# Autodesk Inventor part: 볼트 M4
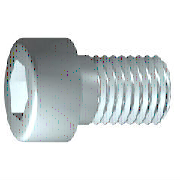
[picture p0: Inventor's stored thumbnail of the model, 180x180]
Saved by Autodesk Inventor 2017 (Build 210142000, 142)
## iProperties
IsCustomPart: 0
Created: 2012-02
Part Number: 볼트 M4
Material: 스테인리스강
Description: 6각 소켓 머리 캡 나사
Document SubType Name: Modeling
Standard: ISO 4762
Designer: mduedu
Standard Revision: Fourth edition 2004-03-01
Standards Organization: ISO
Language: ko-KR
Size Designation: M4 x 12
Categories: <MemberInstance><Categories><Category DisplayName="조임쇠" InternalName="e4da775c-781d-43d5-af7c-5136215cf5a6" Mnemonic="FSTN"><Category DisplayName="볼트" InternalN
Density: 8.08 g/cm^3
Mass: 2.2972 g
Surface Area: 3.30853 cm^2
Volume: 0.284306 cm^3
Appearance: 반광택
Author: mduedu
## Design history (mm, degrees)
sketch "스케치1"
  geometry: L1 (-1, 0)-(12, 0); L2 (12, 0)-(12, 2); L3 (12, 2)-(1.75, 2); L4 (1.75, 2)-(1.32, 2); L5 (1.32, 2)-(0, 2); L6 (0, 2)-(0, 3.5); L7 (0, 3.5)-(-4, 3.5); L8 (-4, 3.5)-(-4, 1.732); L9 (-4, 1.732)-(-2, 1.732); L10 (-2, 1.732)-(-1, 0); L11 (-7.2, 0)-(15.2, 0) reference; L12 (0, -0.7)-(0, 4.2) reference; L13 (1.75, 2)-(0, 2)
  constraints: 22 end point, 6 parallel, 2 collinear, 2 perpendicular, 1 horizontal, 1 point on line
  dimensions: "d1" = 10.25 distance from line of L3.end L2 (= GEL); "d2" = 0.42952 distance of L4.end L3.end (computed from GAL); "d3" = 4 distance between parallel lines of L8 L6 (= KOH); "d4" = 2 distance of L8.end L9.end (= INTI); "d5" = 60 deg angle of L10 L1; "d6" = 4 diameter of L3 L1 (= GD); "d7" = 4 diameter of L5 L1 (= BDM); "d8" = 3.4641 diameter of L9 L1 (= 1.1547 x SW); "d9" = 7 diameter of L7 L1 (= KOD); "d26" = 12 distance between parallel lines of L12 L2 (= NLG)
revolve "본체" sketch "스케치1" stored, may be unused: angle "d10" = 90 deg
sketch "스케치2"
  geometry: L1 (0, -4.9)-(0, 4.9) reference; L2 (-4.9, 0)-(4.9, 0) reference; L3 (1.732, 0)-(0.866, -1.5); L4 (0.866, -1.5)-(-0.866, -1.5); L5 (-0.866, -1.5)-(-1.732, 0); L6 (-1.732, 0)-(-0.866, 1.5); L7 (-0.866, 1.5)-(0.866, 1.5); L8 (0.866, 1.5)-(1.732, 0); 2 further points
  constraints: 12 end point, 1 coincident, 1 horizontal alignment, 1 point on line, 12 other
extrude "슬롯" join sketch "스케치2" stored distance "d11" = 10; taper "d12" = 0 deg
workplane "Work Plane1"
fillet "Fillet2" dims "d30" = 0.1 (= R)
body "Solid1"
fillet "모깎기1" dims "d17" = 0.4 (= RR)
feature "스레드" dims "d13" = 10.25 (= GEL), "d14" = 0
chamfer "모따기1" distance "d15" = 0.42941 (= -0.5 x SPD + 0.5 x GD); stored, may be unused: second distance "d16" = 0.42941 (= GUL), angle "d27" = 45 deg
other parameters: "GD" = 4 [user parameter; used in 2 equation terms], "NLG" = 12 [user parameter; used in 1 equation term], "GEL" = 10.25 [user parameter; used in 2 equation terms], "KOD" = 7 [user parameter; used in 1 equation term], "KOH" = 4 [user parameter; used in 1 equation term], "INTI" = 2 [user parameter; used in 1 equation term], "GAL" = 0.42941 (= 0.61345 x PTC) [user parameter; used in 1 equation term], "GUL" = 0.42941 (= 0.61345 x PTC) [user parameter; used in 1 equation term], "BDM" = 4 (= NND) [user parameter; used in 1 equation term], "SW" = 3 [user parameter; used in 2 equation terms], "RR" = 0.4 [user parameter; used in 1 equation term], "SPD" = 3.14117 (= NND - 1.2269 x PTC) [user parameter; used in 1 equation term], "d19" = 0, "d28" = 0, "d29" = 0, "R" = 0.1 [user parameter; used in 1 equation term], "TOA" = 30 deg [user parameter], "GD1" = 3.14117 (= THREADDIA - 1.2269 x PTC) [user parameter], "THREADDIA" = 4 [user parameter; used in 1 equation term], "FAWI" = 45 deg [user parameter], "TPU" = 14.28571 (computed from PTC) [user parameter], "PTC" = 0.7 [user parameter; used in 5 equation terms], "NND" = 4 [user parameter; used in 2 equation terms], "E0" = 3.465 (= 1.155 x SW) [user parameter]
